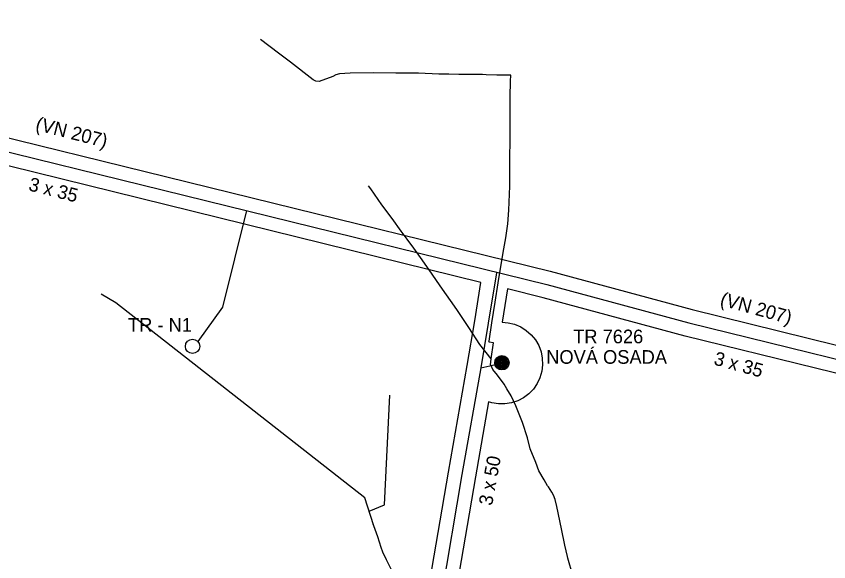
# Model space of a CAD drawing. Extents: x -439095 to -431527, y -1129525 to -1119219.
# Drawn here: x -438756 to -438161, y -1124004 to -1123605 of the extents above; entities that cross this region are included whole.
import ezdxf

# ---------------------------------------------------------------- set-up
doc = ezdxf.new("R2010")
doc.units = 0
for name, color, linetype in [('Hranice reseneho uzemi', 7, 'Continuous'), ('UZEMNI REZERVA', 7, 'Continuous'), ('Vrstva 11', 7, 'Continuous'), ('Vrstva 13', 7, 'Continuous'), ('Vrstva 19', 7, 'Continuous'), ('Vrstva 21', 7, 'Continuous'), ('ZU', 7, 'Continuous')]:
    doc.layers.add(name, color=color, linetype=linetype)

msp = doc.modelspace()

# ---------------------------------------------------------------- linework, layer by layer
at = {"layer": 'Hranice reseneho uzemi'}
for points in [[(-439088.23, -1123614.34), (-439007.22, -1123640.64), (-438835.74, -1123685.67), (-438367.56, -1123800.96), (-438263.63, -1123828.96), (-438072.97, -1123875.97)], [(-438587.35, -1123746.84), (-438604.89, -1123817.59), (-438623.06, -1123842.59)], [(-438404.4, -1123792.3), (-438410.29, -1123829.14), (-438410.29, -1123829.15), (-438415.85, -1123861.97), (-438429.64, -1123939.97), (-438444.63, -1124028.49), (-438464.17, -1124139.38), (-438460.66, -1124232.64), (-438453.88, -1124338.49), (-438452.62, -1124356.08), (-438452.62, -1124356.09), (-438451.55, -1124372.99), (-438451.29, -1124373.35), (-438451.28, -1124373.5)], [(-438415.85, -1123861.97), (-438409.29, -1123860.54), (-438400.33, -1123858.27)]]:
    msp.add_lwpolyline(points, dxfattribs=at)
at = {"layer": 'UZEMNI REZERVA'}
for points in [[(-438348.43, -1124013.96), (-438352.09, -1124001.36), (-438352.42, -1124000), (-438354.4, -1123991.89), (-438356.75, -1123979.88), (-438360.08, -1123963.49), (-438361.26, -1123958.26), (-438362.47, -1123955.24), (-438363.82, -1123953.07), (-438366.34, -1123949.03), (-438366.87, -1123948.28), (-438369.46, -1123943.92), (-438373.3, -1123937.43), (-438375.49, -1123931.35), (-438379.59, -1123921.28), (-438381.61, -1123913.23), (-438385.16, -1123901.92), (-438390.07, -1123889.68), (-438393.66, -1123882.5), (-438396.73, -1123877.32), (-438398.7, -1123873.81), (-438403.66, -1123867.32), (-438406.88, -1123863.05), (-438407.78, -1123861.47), (-438408.31, -1123860.34), (-438408.64, -1123859.66), (-438408.3, -1123855.43), (-438408.25, -1123855.34), (-438406.42, -1123843.73), (-438406.67, -1123843.71), (-438409.51, -1123843.05), (-438409.81, -1123842.97), (-438409.75, -1123842.52), (-438409.72, -1123842.39), (-438407.63, -1123829.12), (-438405.27, -1123813.93), (-438403.06, -1123799.62), (-438399.32, -1123777.55), (-438397.48, -1123766.86), (-438396.04, -1123756.43), (-438395.2, -1123746.58), (-438394.54, -1123729), (-438394.59, -1123705.84), (-438394.36, -1123698.06), (-438394.42, -1123691.57), (-438394.25, -1123679.01), (-438394.2, -1123663.42), (-438394.01, -1123652.09), (-438394.01, -1123652.09), (-438393.93, -1123647.78), (-438398.72, -1123647.69), (-438403.99, -1123647.59), (-438411.96, -1123647.4), (-438414.67, -1123647.28), (-438416.76, -1123647.28), (-438422.68, -1123647.2), (-438431.88, -1123647.07), (-438439.13, -1123646.98), (-438441.33, -1123646.99), (-438446.54, -1123646.82), (-438461.52, -1123646.12), (-438465.53, -1123646.15), (-438471.33, -1123646.24), (-438478.07, -1123646.28), (-438494.05, -1123645.86), (-438511.39, -1123646.09), (-438519.36, -1123646.73), (-438521.82, -1123647.41), (-438524.19, -1123648.62), (-438534.05, -1123652.24), (-438536.59, -1123652.07), (-438538.5, -1123650.98), (-438555, -1123638.1), (-438563.84, -1123631.64), (-438577.05, -1123621.48)], [(-438408.25, -1123855.34), (-438416.53, -1123844.85), (-438424.47, -1123832.44), (-438433.3, -1123819.27), (-438445.58, -1123801.82), (-438451.49, -1123793.27), (-438458.79, -1123782.93), (-438464.91, -1123774.38), (-438469.79, -1123767.78), (-438474.14, -1123761.8), (-438480.62, -1123752.7), (-438488.26, -1123742.54), (-438496.28, -1123730.79), (-438497.91, -1123728.69)], [(-438494.46, -1123976.81), (-438500.68, -1123957.08), (-438683.04, -1123814.28), (-438693.59, -1123807.95)], [(-438497.57, -1123966.94), (-438486.39, -1123962.28), (-438482.43, -1123881.88)], [(-438481.23, -1124009.81), (-438484.76, -1124002.63), (-438487.61, -1123996.81), (-438488.81, -1123993.41), (-438491.27, -1123985.58), (-438494.14, -1123977.51), (-438494.46, -1123976.81), (-438494.8, -1123976.37)]]:
    msp.add_lwpolyline(points, dxfattribs=at)
at = {"layer": 'Vrstva 11'}
for radius in [5.25, 4.55, 3.85, 3.15, 2.45, 1.75, 1.05, 0.35]:
    msp.add_circle((-438400.33, -1123858.27), radius, dxfattribs=at)
at = {"layer": 'Vrstva 19'}
msp.add_circle((-438626.84, -1123846.23), 5.25, dxfattribs=at)
at = {"layer": 'ZU'}
for points in [[(-439086.08, -1123604.53), (-439004.4, -1123631.04), (-438833.27, -1123675.98), (-438365.06, -1123791.27), (-438261.13, -1123819.28), (-438070.53, -1123866.27), (-437988.14, -1123887.48)], [(-438415.66, -1123799.41), (-438838.2, -1123695.36), (-439010.03, -1123650.24), (-439095.38, -1123622.54)], [(-438463.37, -1124345.98), (-438463.86, -1124339.17), (-438470.65, -1124233.15), (-438474.2, -1124138.69), (-438454.48, -1124026.79), (-438439.49, -1123938.26), (-438425.7, -1123860.26), (-438420.16, -1123827.52), (-438415.66, -1123799.41)], [(-438396.17, -1123804.21), (-438400.07, -1123828.55)], [(-437892.75, -1123947.93), (-437892.82, -1123947.87), (-437938.91, -1123922.24), (-437979.96, -1123910.23), (-438075.42, -1123885.67), (-438266.12, -1123838.65), (-438370.06, -1123810.64), (-438396.17, -1123804.21)], [(-438400.07, -1123828.55), (-438395.73, -1123828.9), (-438391.04, -1123830.05), (-438386.6, -1123831.95), (-438382.52, -1123834.53), (-438378.91, -1123837.73), (-438375.85, -1123841.47), (-438373.44, -1123845.65), (-438371.73, -1123850.16), (-438370.76, -1123854.89), (-438370.57, -1123859.72), (-438371.15, -1123864.51), (-438372.49, -1123869.15), (-438374.56, -1123873.51), (-438377.3, -1123877.48), (-438380.65, -1123880.96), (-438384.51, -1123883.87), (-438388.78, -1123886.11), (-438393.36, -1123887.64), (-438398.13, -1123888.41), (-438402.96, -1123888.41), (-438407.72, -1123887.64), (-438410.09, -1123886.85)], [(-438410.09, -1123886.85), (-438419.79, -1123941.67), (-438434.77, -1124030.2), (-438454.13, -1124140.07), (-438450.67, -1124232.14), (-438443.91, -1124337.81), (-438443.42, -1124344.63)]]:
    msp.add_lwpolyline(points, dxfattribs=at)

# ---------------------------------------------------------------- texts
at = {"layer": 'Vrstva 13'}
for s, rotation, p in [('(VN 207)', 345.67636, (-438742.37, -1123687.73)), ('3 x 35', 345.67629, (-438747.48, -1123731.9)), ('(VN 207)', 344.56954, (-438241.26, -1123815.94)), ('3 x 35', 344.56967, (-438245.87, -1123859.41)), ('3 x 50', 79.58638, (-438407.58, -1123963.25))]:
    msp.add_text(s, height=10, rotation=rotation, dxfattribs=at).set_placement(p)
for s, p in [('TR 7626', (-438348.18, -1123843.99)), ('NOVÁ OSADA', (-438367.92, -1123858.99))]:
    msp.add_text(s, height=10, dxfattribs=at).set_placement(p)
at = {"layer": 'Vrstva 21'}
msp.add_text('TR - N1', height=10, dxfattribs=at).set_placement((-438674.06, -1123835.49))

doc.saveas('drawing.dxf')
